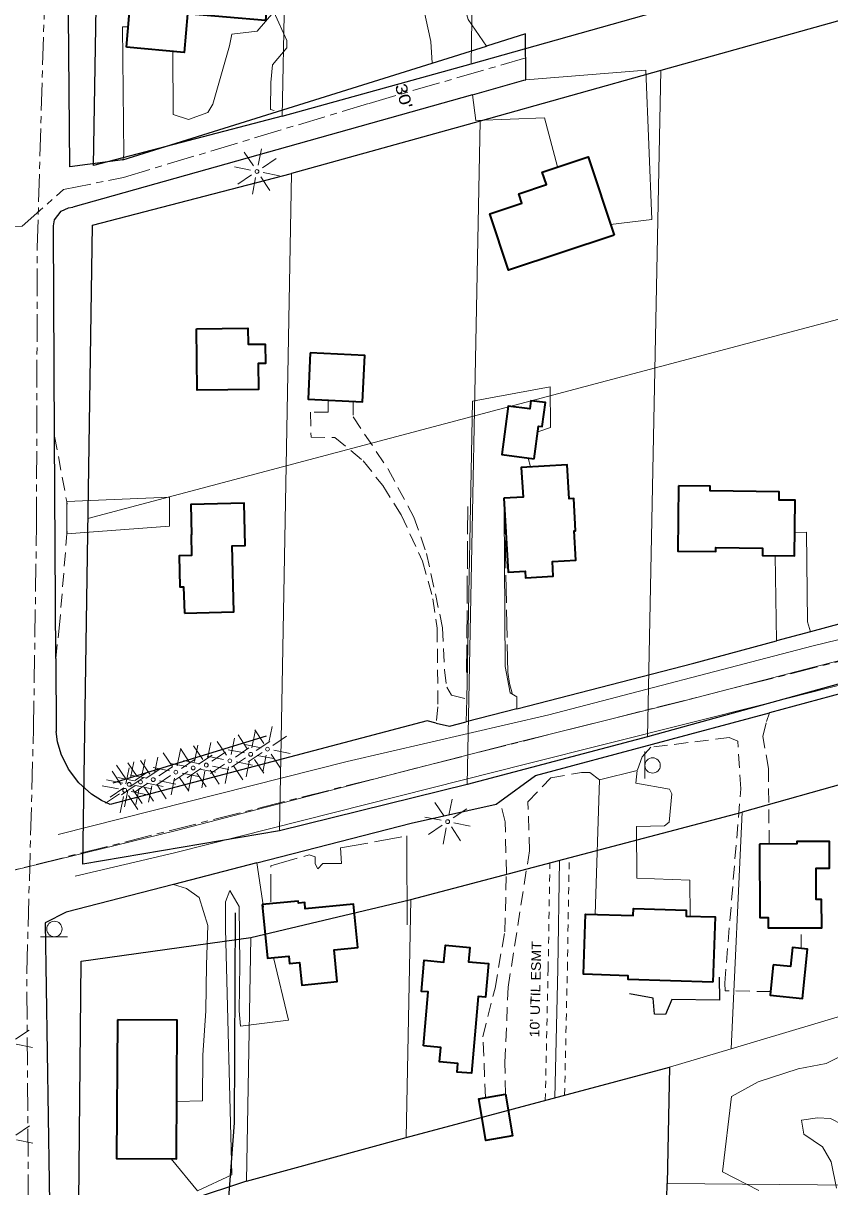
# Model space of a CAD drawing. Extents: x -861682 to -858969, y -1797841 to -1795153.
# Drawn here: x -860995 to -860575, y -1796688 to -1796083 of the extents above; entities that cross this region are included whole.
import ezdxf

# ---------------------------------------------------------------- set-up
doc = ezdxf.new("R2010")
doc.units = 0
doc.header["$LTSCALE"] = 2.4
for name, pattern in [('LONG_DASH_SHORT_DASH', [9.9, 6, -1.2, 1.5, -1.2]), ('LONG_DASHED', [7.5, 6, -1.5]), ('MEDIUM_DASHED', [4.5, 3, -1.5]), ('SHORT_DASHED', [2.7, 1.5, -1.2])]:
    doc.linetypes.add(name, pattern=pattern)
for name, color, linetype, lineweight in [('10', 7, 'Continuous', 25), ('11', 7, 'Continuous', 13), ('12', 7, 'Continuous', 35), ('14', 7, 'Continuous', 25), ('17', 7, 'Continuous', 13), ('18', 7, 'Continuous', 13), ('21', 7, 'Continuous', 13), ('30', 7, 'Continuous', 13), ('32', 7, 'LONG_DASH_SHORT_DASH', 13), ('42', 7, 'Continuous', 25), ('47', 7, 'SHORT_DASHED', 13), ('52', 7, 'LONG_DASHED', 13), ('54', 7, 'Continuous', 13)]:
    doc.layers.add(name, color=color, linetype=linetype, lineweight=lineweight)
doc.layers.add('43', color=7, linetype='Continuous')

msp = doc.modelspace()

# ---------------------------------------------------------------- linework, layer by layer
at = {"layer": '10'}
for p, q in [((-860782.148, -1796103.763), (-860753.902, -1796094.914)), ((-860943.044, -1796154.171), (-860782.148, -1796103.763)), ((-860761.092, -1796120.211), (-860969.057, -1796178.736)), ((-860978.567, -1796297.9), (-860979.119, -1796190.166)), ((-860977.975, -1796413.465), (-860978.567, -1796297.9)), ((-860585.314, -1796399.643), (-860602.967, -1796404.391)), ((-860977.975, -1796413.465), (-860977.781, -1796451.495)), ((-860545.1, -1796425.256), (-860606.635, -1796441.755)), ((-860738.158, -1796439.731), (-860764.405, -1796446.5)), ((-860873.273, -1796519.92), (-860916.639, -1796531.103))]:
    msp.add_line(p, q, dxfattribs=at)
for points in [[(-860943.044, -1796154.171), (-860970.659, -1796157.721), (-860972.218, -1795979.333), (-860974.746, -1795960.452), (-860975.763, -1795883.427)], [(-860733.343, -1796112.403), (-860733.552, -1796088.539), (-860753.902, -1796094.914)], [(-860761.092, -1796120.211), (-860734.4, -1796112.699), (-860733.343, -1796112.403)], [(-860979.119, -1796190.166), (-860979.184, -1796188.476), (-860978.51, -1796185.254), (-860975.204, -1796180.839), (-860971.243, -1796178.985), (-860969.057, -1796178.736)], [(-860526.86, -1796384.004), (-860528.934, -1796384.483), (-860585.314, -1796399.643)], [(-860738.158, -1796439.731), (-860646.097, -1796415.989), (-860602.967, -1796404.391)], [(-860746.895, -1796487.909), (-860728.402, -1796474.404), (-860606.635, -1796441.755)], [(-860780.03, -1796447.146), (-860784.776, -1796446.028), (-860949.566, -1796489.527)], [(-860780.03, -1796447.146), (-860773.174, -1796448.762), (-860764.405, -1796446.5)], [(-860949.566, -1796489.527), (-860954.087, -1796487.399), (-860959.356, -1796484.07), (-860965.921, -1796478.207), (-860971.234, -1796471.19), (-860975.096, -1796463.28), (-860976.95, -1796456.939), (-860977.781, -1796451.495)], [(-860873.273, -1796519.92), (-860793.011, -1796499.223), (-860748.888, -1796489.364), (-860746.895, -1796487.909)], [(-860916.639, -1796531.103), (-860972.545, -1796545.521), (-860983.387, -1796550.997), (-860980.82, -1796719.365)]]:
    msp.add_lwpolyline(points, dxfattribs=at)
at = {"layer": '11', "linetype": 'MEDIUM_DASHED'}
for p, q in [((-860978.567, -1796297.9), (-860972.224, -1796331.883)), ((-860971.961, -1796333.298), (-860972.224, -1796331.883)), ((-860972.074, -1796347.477), (-860972.174, -1796348.729)), ((-860590.236, -1796564.376), (-860590.332, -1796553.672))]:
    msp.add_line(p, q, dxfattribs=at)
at = {"layer": '11'}
for p, q in [((-860730.982, -1796313.817), (-860732.249, -1796309.25)), ((-860972.174, -1796348.729), (-860972.224, -1796331.883)), ((-860603.724, -1796359.986), (-860602.967, -1796404.391)), ((-860764.175, -1796434.622), (-860764.405, -1796446.5)), ((-860695.094, -1796476.632), (-860675.512, -1796471.83)), ((-860697.34, -1796546.686), (-860695.094, -1796476.632)), ((-860869.799, -1796543.002), (-860873.273, -1796519.92))]:
    msp.add_line(p, q, dxfattribs=at)
for points in [[(-860769.837, -1796057.771), (-860763.391, -1796081.002), (-860753.902, -1796094.914)], [(-860789.227, -1796062.991), (-860782.902, -1796092.515), (-860782.148, -1796103.763)], [(-860917.073, -1796097.659), (-860916.785, -1796130.548), (-860908.966, -1796133.079), (-860898.837, -1796129.446), (-860896.275, -1796125.17), (-860887.561, -1796094.848), (-860886.433, -1796088.695), (-860873.214, -1796087.161), (-860864.558, -1796077.161), (-860857.812, -1796091.989), (-860857.779, -1796095.769), (-860865.264, -1796104.578), (-860866.128, -1796113.801), (-860866.241, -1796127.979), (-860864.349, -1796128.414)], [(-860940.264, -1796084.912), (-860943.176, -1796084.938), (-860942.594, -1796151.568), (-860943.044, -1796154.171)], [(-860689.337, -1796187.758), (-860667.963, -1796185.084), (-860671.005, -1796107.369), (-860733.343, -1796112.403)], [(-860717.016, -1796157.814), (-860723.719, -1796132.168), (-860759.386, -1796133.661), (-860761.092, -1796120.211)], [(-860727.188, -1796295.57), (-860720.657, -1796293.294), (-860720.84, -1796272.265), (-860761.182, -1796279.706), (-860764.175, -1796434.622)], [(-860972.174, -1796348.729), (-860918.696, -1796344.647), (-860918.828, -1796329.526), (-860972.224, -1796331.883)], [(-860744.615, -1796336.745), (-860744.144, -1796417.79), (-860741.661, -1796431.474), (-860738.098, -1796433.569), (-860738.158, -1796439.731)], [(-860593.519, -1796348.212), (-860587.382, -1796347.895), (-860586.975, -1796394.442), (-860585.314, -1796399.643)], [(-860647.882, -1796547.601), (-860648.124, -1796528.872), (-860675.76, -1796527.802), (-860675.868, -1796500.88), (-860661.227, -1796500.585), (-860658.873, -1796498.686), (-860657.514, -1796484.039), (-860658.706, -1796481.446), (-860676.194, -1796478.446), (-860675.512, -1796471.83)], [(-860914.943, -1796644.086), (-860901.538, -1796643.716), (-860901.398, -1796619.863), (-860899.836, -1796596.949), (-860899.461, -1796572.859), (-860898.834, -1796552.547), (-860903.38, -1796537.923), (-860910.011, -1796533.227), (-860916.639, -1796531.103)], [(-860917.95, -1796673.813), (-860904.185, -1796690.487), (-860886.27, -1796682.149), (-860889.617, -1796554.163), (-860889.673, -1796540.23), (-860887.335, -1796534.316), (-860882.579, -1796542.563), (-860882.222, -1796572.554), (-860882.597, -1796596.88), (-860881.856, -1796604.907), (-860856.836, -1796601.737), (-860864.668, -1796569.117)]]:
    msp.add_lwpolyline(points, dxfattribs=at)
at = {"layer": '11', "linetype": 'MEDIUM_DASHED'}
for points in [[(-860836.329, -1796279.083), (-860836.275, -1796285.325), (-860845.489, -1796285.406), (-860845.14, -1796298.399), (-860832.851, -1796298.528), (-860818.095, -1796310.686), (-860807.821, -1796323.592), (-860798.236, -1796338.868), (-860787.157, -1796362.873), (-860781.787, -1796382.439), (-860779.526, -1796397.778), (-860779.169, -1796438.654), (-860780.03, -1796447.146)], [(-860823.183, -1796279.741), (-860823.257, -1796287.811), (-860805.06, -1796315.062), (-860791.61, -1796339.991), (-860785.065, -1796358.838), (-860776.693, -1796397.517), (-860775.792, -1796419.485), (-860774.533, -1796428.453), (-860772.133, -1796432.685), (-860764.175, -1796434.622)], [(-860977.975, -1796413.465), (-860976.123, -1796397.842), (-860972.174, -1796348.729)], [(-860606.834, -1796510.05), (-860607.265, -1796470.848), (-860610.166, -1796454.093), (-860608.308, -1796446.292), (-860606.635, -1796441.755)], [(-860606.139, -1796586.888), (-860629.709, -1796586.422), (-860629.962, -1796582.408), (-860621.629, -1796481.297), (-860623.145, -1796456.506), (-860627.64, -1796454.635), (-860668.475, -1796459.758), (-860672.942, -1796464.735), (-860675.512, -1796471.83)], [(-860744.07, -1796640.341), (-860744.335, -1796623.723), (-860742.603, -1796584.513), (-860731.551, -1796513.62), (-860732.362, -1796488.117), (-860720.368, -1796475.553), (-860704.556, -1796472.891), (-860700.069, -1796472.873), (-860695.094, -1796476.632)], [(-860754.481, -1796641.997), (-860755.725, -1796610.307), (-860749.45, -1796585.012), (-860744.371, -1796555.708), (-860743.548, -1796525.476), (-860744.128, -1796498.556), (-860746.895, -1796487.909)]]:
    msp.add_lwpolyline(points, dxfattribs=at)
at = {"layer": '12'}
for points in [[(-860941.194, -1796095.552), (-860936.898, -1796046.365), (-860866.253, -1796052.535), (-860868.798, -1796081.671), (-860909.433, -1796078.122), (-860911.184, -1796098.173)], [(-860687.505, -1796193.286), (-860742.402, -1796211.488), (-860752.103, -1796182.23), (-860735.459, -1796176.712), (-860737.108, -1796171.737), (-860722.74, -1796166.975), (-860724.909, -1796160.429), (-860701.015, -1796152.512)], [(-860904.706, -1796241.972), (-860878.007, -1796241.738), (-860877.935, -1796250.008), (-860868.956, -1796249.93), (-860868.868, -1796260.09), (-860872.648, -1796260.123), (-860872.53, -1796273.59), (-860904.427, -1796273.869)], [(-860845.524, -1796254.451), (-860846.731, -1796278.563), (-860818.447, -1796279.979), (-860817.24, -1796255.867)], [(-860729.021, -1796309.67), (-860726.807, -1796292.637), (-860724.892, -1796292.886), (-860723.266, -1796280.38), (-860730.783, -1796279.403), (-860731.337, -1796283.663), (-860742.625, -1796282.195), (-860745.913, -1796307.473)], [(-860744.91, -1796330.129), (-860742.683, -1796368.626), (-860733.85, -1796368.115), (-860733.648, -1796371.606), (-860719.156, -1796370.767), (-860719.603, -1796363.049), (-860707.429, -1796362.344), (-860708.312, -1796347.092), (-860707.571, -1796347.049), (-860708.542, -1796330.32), (-860710.897, -1796330.457), (-860711.929, -1796312.709), (-860735.791, -1796314.097), (-860734.893, -1796329.547)], [(-860653.993, -1796323.665), (-860654.404, -1796357.695), (-860634.567, -1796357.935), (-860634.542, -1796355.867), (-860610.251, -1796356.161), (-860610.296, -1796359.907), (-860593.662, -1796360.107), (-860593.314, -1796331.181), (-860601.708, -1796331.08), (-860601.656, -1796326.754), (-860637.631, -1796326.322), (-860637.602, -1796323.86)], [(-860910.975, -1796389.947), (-860885.225, -1796389.25), (-860886.152, -1796355.007), (-860879.384, -1796354.824), (-860879.981, -1796332.741), (-860907.713, -1796333.491), (-860907.286, -1796349.268), (-860907.55, -1796349.275), (-860907.268, -1796359.902), (-860913.829, -1796360.076), (-860913.4, -1796376.241), (-860911.45, -1796376.174)], [(-860611.83, -1796510.069), (-860611.677, -1796548.326), (-860607.426, -1796548.309), (-860607.404, -1796553.741), (-860579.537, -1796553.628), (-860579.596, -1796538.987), (-860582.43, -1796538.998), (-860582.493, -1796522.704), (-860575.41, -1796522.677), (-860575.463, -1796508.742), (-860592.47, -1796508.807), (-860592.465, -1796509.995)], [(-860870.538, -1796541.569), (-860867.828, -1796569.425), (-860856.741, -1796568.346), (-860856.368, -1796572.181), (-860851.1, -1796571.669), (-860849.957, -1796583.426), (-860831.507, -1796581.632), (-860833.115, -1796565.099), (-860820.888, -1796563.91), (-860823.087, -1796541.292), (-860848.148, -1796543.729), (-860848.455, -1796540.568), (-860851.682, -1796540.881), (-860851.791, -1796539.753)], [(-860636.102, -1796581.958), (-860680.27, -1796580.481), (-860680.207, -1796578.585), (-860703.41, -1796577.814), (-860702.37, -1796546.519), (-860677.549, -1796547.344), (-860677.426, -1796543.634), (-860649.987, -1796544.544), (-860650.086, -1796547.528), (-860634.977, -1796548.029)], [(-860786.641, -1796615.152), (-860784.156, -1796587.038), (-860787.756, -1796586.72), (-860786.331, -1796570.583), (-860776.003, -1796571.495), (-860775.229, -1796562.726), (-860762.547, -1796563.845), (-860763.209, -1796571.345), (-860752.891, -1796572.256), (-860754.437, -1796589.771), (-860758.138, -1796589.444), (-860761.667, -1796629.381), (-860769.127, -1796628.722), (-860768.739, -1796624.326), (-860778.285, -1796623.483), (-860777.62, -1796615.949)], [(-860604.73, -1796572.86), (-860606.32, -1796588.689), (-860589.493, -1796590.379), (-860586.915, -1796564.71), (-860594.78, -1796563.92), (-860595.768, -1796573.76)], [(-860945.868, -1796601.617), (-860946.287, -1796673.649), (-860915.116, -1796673.83), (-860914.697, -1796601.798)], [(-860744.031, -1796640.25), (-860740.401, -1796661.962), (-860754.302, -1796664.286), (-860757.932, -1796642.574)]]:
    msp.add_lwpolyline(points, close=True, dxfattribs=at)
at = {"layer": '14'}
msp.add_line((-860948.011, -1796478.173), (-860868.356, -1796453.847), dxfattribs=at)
for points in [[(-860953.666, -1796718.076), (-860888.328, -1796698.687), (-860884.96, -1796655.221), (-860884.454, -1796545.875)], [(-860632.807, -1796579.349), (-860632.759, -1796591.393), (-860657.558, -1796591.02), (-860660.833, -1796598.826), (-860666.501, -1796598.613), (-860667.243, -1796590.35), (-860679.533, -1796588.038)]]:
    msp.add_lwpolyline(points, dxfattribs=at)
at = {"layer": '17'}
for p, q in [((-860875.085, -1796157.276), (-860879.875, -1796150.148)), ((-860872.625, -1796156.816), (-860870.899, -1796148.416)), ((-860876.585, -1796159.476), (-860885.047, -1796157.802)), ((-860870.425, -1796158.216), (-860863.329, -1796153.476)), ((-860876.045, -1796161.976), (-860883.271, -1796166.832)), ((-860875.665, -1796171.936), (-860873.985, -1796163.336)), ((-860871.325, -1796162.876), (-860866.525, -1796170.09)), ((-860869.985, -1796160.736), (-860861.505, -1796162.46)), ((-860867.164, -1796457.335), (-860865.438, -1796448.935)), ((-860886.723, -1796463.413), (-860884.997, -1796455.013)), ((-860878.343, -1796460.47), (-860883.133, -1796453.342)), ((-860875.883, -1796460.01), (-860874.157, -1796451.61)), ((-860869.624, -1796457.795), (-860874.414, -1796450.667)), ((-860864.964, -1796458.735), (-860857.868, -1796453.995)), ((-860914.791, -1796469.329), (-860913.065, -1796460.929)), ((-860908.291, -1796467.584), (-860913.081, -1796460.456)), ((-860901.451, -1796466.107), (-860906.241, -1796458.979)), ((-860905.831, -1796467.124), (-860904.105, -1796458.724)), ((-860898.991, -1796465.647), (-860897.265, -1796457.247)), ((-860889.183, -1796463.873), (-860893.973, -1796456.745)), ((-860879.843, -1796462.67), (-860888.305, -1796460.996)), ((-860884.523, -1796464.813), (-860877.427, -1796460.073)), ((-860871.124, -1796459.995), (-860879.586, -1796458.321)), ((-860873.683, -1796461.41), (-860866.587, -1796456.67)), ((-860929.031, -1796473.673), (-860933.821, -1796466.545)), ((-860933.177, -1796474.452), (-860931.451, -1796466.052)), ((-860926.571, -1796473.213), (-860924.845, -1796464.813)), ((-860917.251, -1796469.789), (-860922.041, -1796462.661)), ((-860912.591, -1796470.729), (-860905.495, -1796465.989)), ((-860902.951, -1796468.307), (-860911.413, -1796466.633)), ((-860903.631, -1796468.524), (-860896.535, -1796463.784)), ((-860890.683, -1796466.073), (-860899.145, -1796464.399)), ((-860896.791, -1796467.047), (-860889.695, -1796462.307)), ((-860879.303, -1796465.17), (-860886.529, -1796470.026)), ((-860878.923, -1796475.13), (-860877.243, -1796466.53)), ((-860870.584, -1796462.495), (-860877.81, -1796467.351)), ((-860874.583, -1796466.07), (-860869.783, -1796473.284)), ((-860873.243, -1796463.93), (-860864.763, -1796465.654)), ((-860870.204, -1796472.455), (-860868.524, -1796463.855)), ((-860865.864, -1796463.395), (-860861.064, -1796470.609)), ((-860864.524, -1796461.255), (-860856.044, -1796462.979)), ((-860943.869, -1796479.238), (-860948.659, -1796472.11)), ((-860941.533, -1796476.145), (-860946.323, -1796469.017)), ((-860941.409, -1796478.778), (-860939.683, -1796470.378)), ((-860935.637, -1796474.912), (-860940.427, -1796467.784)), ((-860939.073, -1796475.685), (-860937.347, -1796467.285)), ((-860936.873, -1796477.085), (-860929.777, -1796472.345)), ((-860930.977, -1796475.852), (-860923.881, -1796471.112)), ((-860918.751, -1796471.989), (-860927.213, -1796470.315)), ((-860924.371, -1796474.613), (-860917.275, -1796469.873)), ((-860909.791, -1796469.784), (-860918.253, -1796468.11)), ((-860909.251, -1796472.284), (-860916.477, -1796477.14)), ((-860902.411, -1796470.807), (-860909.637, -1796475.663)), ((-860904.531, -1796473.184), (-860899.731, -1796480.398)), ((-860903.191, -1796471.044), (-860894.711, -1796472.768)), ((-860902.031, -1796480.767), (-860900.351, -1796472.167)), ((-860897.691, -1796471.707), (-860892.891, -1796478.921)), ((-860890.143, -1796468.573), (-860897.369, -1796473.429)), ((-860896.351, -1796469.567), (-860887.871, -1796471.291)), ((-860889.763, -1796478.533), (-860888.083, -1796469.933)), ((-860885.423, -1796469.473), (-860880.623, -1796476.687)), ((-860884.083, -1796467.333), (-860875.603, -1796469.057)), ((-860943.033, -1796478.345), (-860951.495, -1796476.671)), ((-860937.137, -1796477.112), (-860945.599, -1796475.438)), ((-860939.209, -1796480.178), (-860932.113, -1796475.438)), ((-860930.531, -1796475.873), (-860938.993, -1796474.199)), ((-860929.991, -1796478.373), (-860937.217, -1796483.229)), ((-860930.537, -1796478.372), (-860922.057, -1796480.096)), ((-860918.211, -1796474.489), (-860925.437, -1796479.345)), ((-860923.931, -1796477.133), (-860915.451, -1796478.857)), ((-860917.831, -1796484.449), (-860916.151, -1796475.849)), ((-860913.491, -1796475.389), (-860908.691, -1796482.603)), ((-860912.151, -1796473.249), (-860903.671, -1796474.973)), ((-860908.871, -1796482.244), (-860907.191, -1796473.644)), ((-860945.369, -1796481.438), (-860953.831, -1796479.764)), ((-860944.829, -1796483.938), (-860952.055, -1796488.794)), ((-860942.493, -1796480.845), (-860949.719, -1796485.701)), ((-860944.449, -1796493.898), (-860942.769, -1796485.298)), ((-860936.597, -1796479.612), (-860943.823, -1796484.468)), ((-860942.113, -1796490.805), (-860940.433, -1796482.205)), ((-860940.109, -1796484.838), (-860935.309, -1796492.052)), ((-860938.769, -1796482.698), (-860930.289, -1796484.422)), ((-860937.773, -1796481.745), (-860932.973, -1796488.959)), ((-860936.433, -1796479.605), (-860927.953, -1796481.329)), ((-860936.217, -1796489.572), (-860934.537, -1796480.972)), ((-860931.877, -1796480.512), (-860927.077, -1796487.726)), ((-860929.611, -1796488.333), (-860927.931, -1796479.733)), ((-860925.271, -1796479.273), (-860920.471, -1796486.487)), ((-860775.921, -1796495.539), (-860780.711, -1796488.411)), ((-860773.461, -1796495.079), (-860771.735, -1796486.679)), ((-860777.421, -1796497.739), (-860785.883, -1796496.065)), ((-860771.261, -1796496.479), (-860764.165, -1796491.739)), ((-860776.881, -1796500.239), (-860784.107, -1796505.095)), ((-860776.501, -1796510.199), (-860774.821, -1796501.599)), ((-860772.161, -1796501.139), (-860767.361, -1796508.353)), ((-860770.821, -1796498.999), (-860762.341, -1796500.723)), ((-860998.931, -1796611.691), (-860991.835, -1796606.951)), ((-860998.491, -1796614.211), (-860990.011, -1796615.935)), ((-860998.731, -1796661.52), (-860991.635, -1796656.78)), ((-860998.291, -1796664.04), (-860989.811, -1796665.764))]:
    msp.add_line(p, q, dxfattribs=at)
for centre in [(-860873.285, -1796160.176), (-860867.824, -1796460.695), (-860887.383, -1796466.773), (-860876.543, -1796463.37), (-860915.451, -1796472.689), (-860906.491, -1796470.484), (-860899.651, -1796469.007), (-860939.733, -1796479.045), (-860933.837, -1796477.812), (-860927.231, -1796476.573), (-860942.069, -1796482.138), (-860774.121, -1796498.439)]:
    msp.add_circle(centre, 1, dxfattribs=at)
at = {"layer": '18'}
msp.add_lwpolyline([(-860612.288, -1796690.262), (-860631.22, -1796680.655), (-860626.418, -1796641.433), (-860612.514, -1796633.82), (-860591.759, -1796627.124), (-860577.128, -1796624.232), (-860566.051, -1796618.756), (-860554.02, -1796615.401), (-860537.457, -1796623.364), (-860516.838, -1796641.466), (-860514.411, -1796657.752), (-860514.343, -1796674.755), (-860518.535, -1796689.414), (-860532.734, -1796682.15), (-860540.814, -1796669.429), (-860556.644, -1796667.84), (-860568.971, -1796656.081), (-860574.889, -1796652.798), (-860581.738, -1796652.59), (-860589.999, -1796653.804), (-860588.789, -1796661.12), (-860579.08, -1796667.693), (-860574.562, -1796675.469), (-860571.909, -1796689.156)], dxfattribs=at)
at = {"layer": '21'}
for p, q in [((-860671.524, -1796475.963), (-860671.582, -1796461.959)), ((-860971.888, -1796558.317), (-860985.892, -1796558.371))]:
    msp.add_line(p, q, dxfattribs=at)
for centre in [(-860667.493, -1796469.2), (-860978.65, -1796554.284)]:
    msp.add_circle(centre, 4, dxfattribs=at)
at = {"layer": '30'}
for p, q in [((-860761.9, -1796104.1), (-860758.477, -1795919.848)), ((-860860.091, -1796131.371), (-860856.81, -1795945.973)), ((-860670.175, -1796454.27), (-860663.246, -1796107.683)), ((-860763.871, -1796479.071), (-860757.182, -1796134.019)), ((-860861.64, -1796503.292), (-860855.359, -1796161.267)), ((-860961.174, -1796340.681), (-860367.4, -1796182.928)), ((-860795.598, -1796662.739), (-860793.193, -1796538.992)), ((-860878.673, -1796685.416), (-860876.438, -1796558.754)), ((-860658.721, -1796626.096), (-860626.627, -1796616.6)), ((-860514.881, -1796687.977), (-860659.957, -1796686.663))]:
    msp.add_line(p, q, dxfattribs=at)
for points in [[(-860536.116, -1796469.701), (-860539.529, -1796590.575), (-860626.627, -1796616.6), (-860620.958, -1796493.44)], [(-860718.3, -1796642.046), (-860716.82, -1796574.948), (-860715.899, -1796518.55)]]:
    msp.add_lwpolyline(points, dxfattribs=at)
at = {"layer": '32'}
for points in [[(-861016.908, -1797697.112), (-861016.908, -1797629.868), (-861015.071, -1797572.938), (-861015.071, -1797447.139), (-861012.317, -1797374.599), (-861007.726, -1797281.857), (-861003.087, -1797084.148), (-860992.207, -1796696.344), (-860992.984, -1796576.661), (-860989.487, -1796449.983), (-860987.933, -1796343.901), (-860987.544, -1796199.737), (-860984.047, -1796080.831), (-860987.933, -1795887.705), (-860991.735, -1795769.455)], [(-861643.143, -1796342.695), (-861572.843, -1796319.262), (-861541.729, -1796312.003), (-861465.815, -1796297.069), (-861385.338, -1796273.839), (-861355.885, -1796263.468), (-861210.278, -1796225.718), (-861080.021, -1796195.85), (-861059.279, -1796192.323), (-861048.079, -1796191.078), (-860995.395, -1796188.589), (-860973.824, -1796169.507), (-860942.711, -1796163.285), (-860814.942, -1796124.705), (-860733.443, -1796101.033)], [(-861651.105, -1796687.844), (-861333.558, -1796608.31), (-860734.009, -1796456.297), (-860402.78, -1796372.876), (-860279.286, -1796339.345), (-860213.04, -1796323.806), (-860166.423, -1796315.627), (-860126.348, -1796310.72), (-860089.545, -1796308.267), (-860056.831, -1796312.356), (-859995.492, -1796331.984), (-859827.834, -1796395.777), (-859764.042, -1796414.588), (-859688.8, -1796435.852), (-859629.915, -1796444.03), (-859562.034, -1796449.756), (-859471.253, -1796448.938), (-859395.193, -1796443.213), (-859240.62, -1796421.131), (-859002.083, -1796383.657)]]:
    msp.add_lwpolyline(points, dxfattribs=at)
at = {"layer": '42'}
for p, q in [((-860761.9, -1796104.1), (-860666.261, -1796077.293)), ((-860563.945, -1796079.865), (-860663.246, -1796107.683)), ((-860860.091, -1796131.371), (-860761.9, -1796104.1)), ((-860663.246, -1796107.683), (-860757.182, -1796134.019)), ((-860757.182, -1796134.019), (-860855.359, -1796161.267)), ((-860570.941, -1796426.918), (-860670.175, -1796454.27)), ((-860670.175, -1796454.27), (-860763.871, -1796479.071)), ((-860536.116, -1796469.701), (-860620.958, -1796493.44)), ((-860763.871, -1796479.071), (-860861.64, -1796503.292)), ((-860793.193, -1796538.992), (-860620.958, -1796493.44)), ((-860876.438, -1796558.754), (-860793.193, -1796538.992)), ((-860795.598, -1796662.739), (-860658.721, -1796626.096)), ((-860658.721, -1796626.096), (-860659.957, -1796686.663)), ((-860878.673, -1796685.416), (-860795.598, -1796662.739)), ((-860661.564, -1796767.058), (-860659.957, -1796686.663))]:
    msp.add_line(p, q, dxfattribs=at)
for points in [[(-860860.091, -1796131.371), (-860958.277, -1796157.102), (-860955.102, -1795971.99)], [(-860861.64, -1796503.292), (-860963.86, -1796520.607), (-860958.897, -1796188.151), (-860855.359, -1796161.267)], [(-860878.673, -1796685.416), (-860966.096, -1796714.466), (-860964.664, -1796570.952), (-860876.438, -1796558.754)]]:
    msp.add_lwpolyline(points, dxfattribs=at)
at = {"layer": '47'}
for points in [[(-860723.331, -1796643.393), (-860721.819, -1796574.852), (-860720.921, -1796519.878)], [(-860713.269, -1796640.699), (-860711.821, -1796575.044), (-860710.877, -1796517.221)]]:
    msp.add_lwpolyline(points, dxfattribs=at)
at = {"layer": '52'}
msp.add_line((-860764.309, -1796420.891), (-860763.551, -1796333.129), dxfattribs=at)
for points in [[(-860740.494, -1796431.58), (-860741.847, -1796426.574), (-860742.795, -1796420.62), (-860744.401, -1796342.081)], [(-860866.057, -1796540.136), (-860866.132, -1796521.479), (-860846.081, -1796515.731), (-860843.007, -1796516.663), (-860842.992, -1796520.442), (-860841.565, -1796523.034), (-860838.978, -1796520.189), (-860829.296, -1796520.151), (-860829.8, -1796512.123), (-860795.346, -1796505.845), (-860795.302, -1796516.708), (-860795.268, -1796525.21), (-860795.218, -1796537.726), (-860795.158, -1796552.604)]]:
    msp.add_lwpolyline(points, dxfattribs=at)
at = {"layer": '54'}
for points in [[(-860172.631, -1796317.253), (-860204.018, -1796322.811), (-860236.107, -1796330.26), (-860268.193, -1796338.182), (-860308.776, -1796347.556), (-860380.023, -1796366.026), (-860439.712, -1796381.144), (-860499.871, -1796396.736), (-860533.844, -1796405.374), (-860583.86, -1796418.091), (-860653.219, -1796436.08), (-860743.108, -1796458.404), (-860803.739, -1796473.997), (-860915.799, -1796503.257), (-861038.012, -1796533.031), (-861123.178, -1796555.335), (-861206.46, -1796575.979), (-861319.702, -1796605.009), (-861464.557, -1796642.43), (-861630.889, -1796683.009), (-861651.109, -1796688.034)], [(-860357.714, -1796346.597), (-860443.038, -1796371.209), (-860509.283, -1796388.801), (-860584.737, -1796407.182), (-860721.476, -1796442.876), (-860826.415, -1796467.186), (-860976.604, -1796505.123)], [(-860326.19, -1796362.976), (-860392.479, -1796381.19), (-860489.207, -1796405.903), (-860542.286, -1796420.286), (-860608.581, -1796437.082), (-860732.913, -1796468.281), (-860916.226, -1796514.595), (-860967.897, -1796526.846)]]:
    msp.add_lwpolyline(points, dxfattribs=at)

# ---------------------------------------------------------------- texts
at = {"layer": '43', "width": 1.25}
msp.add_text("30'", height=6, rotation=286.118, dxfattribs=at).set_placement((-860801.587, -1796115.46))
at = {"layer": '47', "width": 1.1}
msp.add_text("10' UTIL ESMT", height=5, rotation=88.739, dxfattribs=at).set_placement((-860726.443, -1796610.731))

doc.saveas('drawing.dxf')
